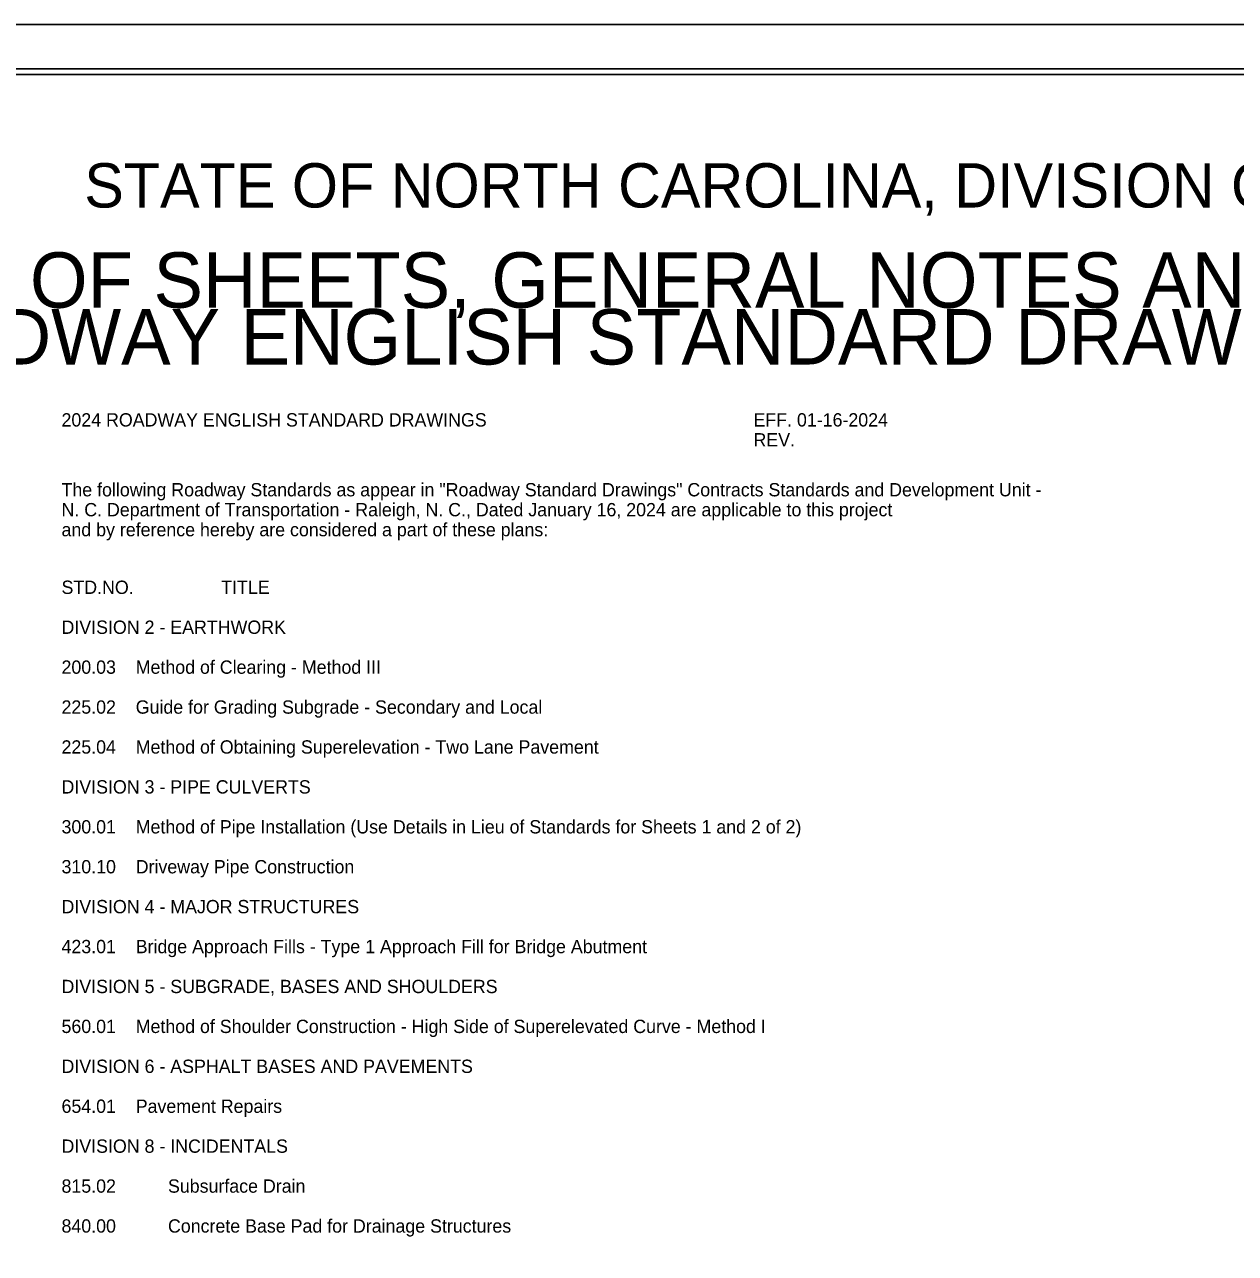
# Model space of a CAD drawing. Extents: x 775818 to 777502, y 889228 to 890323.
# Drawn here: x 776410 to 776956, y 889769 to 890323 of the extents above; entities that cross this region are included whole.
import ezdxf

# ---------------------------------------------------------------- set-up
doc = ezdxf.new("R2010")
doc.units = 0
for name, color, linetype in [('Sheet Cutting Line CELL', 7, 'Continuous'), ('Sheet Data Field CELL', 7, 'Continuous'), ('Sheet Data Text CELL', 7, 'Continuous'), ('Sheet Plan CELL', 7, 'Continuous'), ('Sheet Plot Border Inside CELL', 7, 'Continuous'), ('Sheet Plot Border Outside CELL', 7, 'Continuous'), ('Sheet Symbology CELL', 7, 'Continuous')]:
    doc.layers.add(name, color=color, linetype=linetype)

msp = doc.modelspace()

# ---------------------------------------------------------------- linework, layer by layer
at = {"layer": 'Sheet Cutting Line CELL'}
msp.add_line((777501.78, 890323.31), (775818.28, 890323.31), dxfattribs=at)
at = {"layer": 'Sheet Plan CELL'}
msp.add_lwpolyline([(777484.78, 890300.81), (775984.78, 890300.81), (775984.78, 889250.81), (777484.78, 889250.81)], close=True, dxfattribs=at)
at = {"layer": 'Sheet Plot Border Inside CELL'}
msp.add_lwpolyline([(775831.28, 889248.31), (777497.28, 889248.31), (777497.28, 890303.31), (775831.28, 890303.31)], close=True, dxfattribs=at)
at = {"layer": 'Sheet Plot Border Outside CELL'}
msp.add_lwpolyline([(775818.28, 889228.31), (777501.78, 889228.31), (777501.78, 890323.31), (775818.28, 890323.31)], close=True, dxfattribs=at)

# ---------------------------------------------------------------- texts
at = {"layer": 'Sheet Data Field CELL'}
for s, p in [('INDEX OF SHEETS, GENERAL NOTES AND 2024 ', (776300.8, 890195.61)), ('ROADWAY ENGLISH STANDARD DRAWINGS', (776325.23, 890170.03))]:
    msp.add_text(s, height=25, dxfattribs=at).set_placement(p)
at = {"layer": 'Sheet Data Text CELL'}
for s, p in [('2024 ROADWAY ENGLISH STANDARD DRAWINGS', (776426.49, 890142.07)), ('EFF. 01-16-2024', (776738.49, 890142.07)), ('REV.', (776738.49, 890133.07)), ('The following Roadway Standards as appear in "Roadway Standard Drawings" Contracts Standards and Development Unit -', (776426.49, 890110.57)), ('N. C. Department of Transportation - Raleigh, N. C., Dated January 16, 2024 are applicable to this project', (776426.49, 890101.57)), ('and by reference hereby are considered a part of these plans:', (776426.49, 890092.57)), ('STD.NO.', (776426.49, 890066.57)), ('TITLE', (776498.49, 890066.57)), ('DIVISION 2 - EARTHWORK', (776426.49, 890048.57)), ('200.03    Method of Clearing - Method III', (776426.49, 890030.57)), ('225.02    Guide for Grading Subgrade - Secondary and Local', (776426.49, 890012.57)), ('225.04    Method of Obtaining Superelevation - Two Lane Pavement', (776426.49, 889994.57)), ('DIVISION 3 - PIPE CULVERTS', (776426.49, 889976.57)), ('300.01    Method of Pipe Installation (Use Details in Lieu of Standards for Sheets 1 and 2 of 2)', (776426.49, 889958.57)), ('310.10    Driveway Pipe Construction ', (776426.49, 889940.57)), ('DIVISION 4 - MAJOR STRUCTURES', (776426.49, 889922.57)), ('423.01    Bridge Approach Fills - Type 1 Approach Fill for Bridge Abutment', (776426.49, 889904.57)), ('DIVISION 5 - SUBGRADE, BASES AND SHOULDERS', (776426.49, 889886.57)), ('560.01    Method of Shoulder Construction - High Side of Superelevated Curve - Method I', (776426.49, 889868.57)), ('DIVISION 6 - ASPHALT BASES AND PAVEMENTS', (776426.49, 889850.57)), ('654.01    Pavement Repairs', (776426.49, 889832.57)), ('DIVISION 8 - INCIDENTALS', (776426.49, 889814.57)), ('815.02', (776426.49, 889796.57)), ('Subsurface Drain', (776474.49, 889796.57)), ('840.00', (776426.49, 889778.57)), ('Concrete Base Pad for Drainage Structures', (776474.49, 889778.57))]:
    msp.add_text(s, height=6, dxfattribs=at).set_placement(p)
at = {"layer": 'Sheet Symbology CELL'}
msp.add_text('STATE OF NORTH CAROLINA, DIVISION OF HIGHWAYS', height=20, dxfattribs=at).set_placement((776436.75, 890240.81))

doc.saveas('drawing.dxf')
